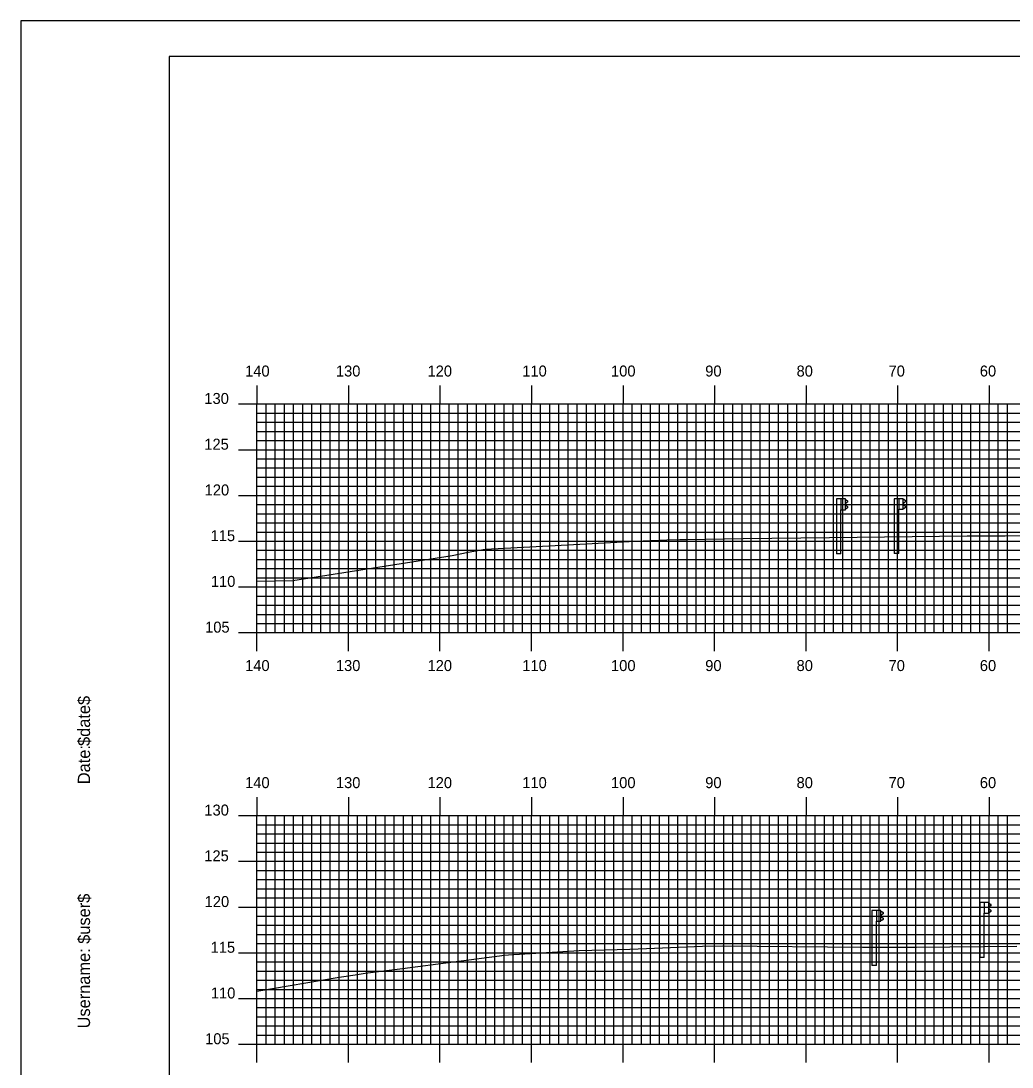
# Model space of a CAD drawing. Extents: x 1754314 to 1754654, y 442591 to 442811.
# Drawn here: x 1754314.2 to 1754422.5, y 442696.2 to 442810.5 of the extents above; entities that cross this region are included whole.
import ezdxf

# ---------------------------------------------------------------- set-up
doc = ezdxf.new("R2010")
doc.units = 0
for name, color, linetype in [('BORDER', 7, 'Continuous'), ('H_V ANNOTATION', 7, 'Continuous'), ('M_Guardrail', 7, 'Continuous'), ('M_Roadway_Centerline', 7, 'Continuous'), ('MAJOR', 7, 'Continuous'), ('MINOR', 7, 'Continuous'), ('PLOT BOUNDARY', 7, 'Continuous'), ('S_Roadway_Centerline', 7, 'Continuous')]:
    doc.layers.add(name, color=color, linetype=linetype)

msp = doc.modelspace()

# ---------------------------------------------------------------- linework, layer by layer
at = {"layer": 'BORDER'}
msp.add_lwpolyline([(1754330.4, 442596.67), (1754650.4, 442596.67), (1754650.4, 442806.67), (1754330.4, 442806.67)], close=True, dxfattribs=at)
at = {"layer": 'M_Guardrail'}
for p, q in [((1754403.31, 442758.28), (1754403.31, 442752.28)), ((1754403.81, 442758.28), (1754403.31, 442758.28)), ((1754404.29, 442758.28), (1754403.81, 442758.28)), ((1754403.81, 442758.28), (1754403.81, 442757.11)), ((1754404.29, 442757.11), (1754404.29, 442758.28)), ((1754404.29, 442758.21), (1754404.38, 442758.19)), ((1754404.31, 442757.74), (1754404.31, 442757.65)), ((1754404.54, 442757.94), (1754404.34, 442757.81)), ((1754404.34, 442757.59), (1754404.54, 442757.45)), ((1754404.39, 442758.19), (1754404.54, 442758.09)), ((1754409.63, 442758.31), (1754409.63, 442752.31)), ((1754410.13, 442758.31), (1754409.63, 442758.31)), ((1754410.62, 442758.31), (1754410.13, 442758.31)), ((1754410.13, 442758.31), (1754410.13, 442757.15)), ((1754410.62, 442757.15), (1754410.62, 442758.31)), ((1754410.62, 442758.24), (1754410.7, 442758.23)), ((1754410.63, 442757.78), (1754410.63, 442757.69)), ((1754410.86, 442757.98), (1754410.66, 442757.84)), ((1754410.66, 442757.62), (1754410.86, 442757.48)), ((1754410.71, 442758.22), (1754410.86, 442758.12)), ((1754410.86, 442757.34), (1754410.71, 442757.24)), ((1754403.81, 442752.28), (1754403.81, 442757.11)), ((1754403.81, 442757.11), (1754404.29, 442757.11)), ((1754404.38, 442757.2), (1754404.29, 442757.19)), ((1754404.54, 442757.31), (1754404.39, 442757.21)), ((1754410.13, 442752.31), (1754410.13, 442757.15)), ((1754410.13, 442757.15), (1754410.62, 442757.15)), ((1754410.7, 442757.23), (1754410.62, 442757.22)), ((1754403.81, 442752.28), (1754403.31, 442752.28)), ((1754410.13, 442752.31), (1754409.63, 442752.31)), ((1754418.97, 442714.16), (1754418.97, 442708.16)), ((1754419.46, 442714.16), (1754418.97, 442714.16)), ((1754419.95, 442714.16), (1754419.46, 442714.16)), ((1754419.46, 442714.16), (1754419.46, 442712.99)), ((1754419.95, 442712.99), (1754419.95, 442714.16)), ((1754419.95, 442714.08), (1754420.03, 442714.07)), ((1754420.05, 442714.06), (1754420.19, 442713.96)), ((1754407.2, 442713.28), (1754407.2, 442707.28)), ((1754407.69, 442713.28), (1754407.2, 442713.28)), ((1754408.18, 442713.28), (1754407.69, 442713.28)), ((1754407.69, 442713.28), (1754407.69, 442712.11)), ((1754408.18, 442712.11), (1754408.18, 442713.28)), ((1754408.18, 442713.21), (1754408.27, 442713.19)), ((1754408.2, 442712.74), (1754408.2, 442712.65)), ((1754408.43, 442712.94), (1754408.23, 442712.81)), ((1754408.28, 442713.19), (1754408.43, 442713.09)), ((1754419.46, 442708.16), (1754419.46, 442712.99)), ((1754419.46, 442712.99), (1754419.95, 442712.99)), ((1754420.03, 442713.08), (1754419.95, 442713.06)), ((1754419.96, 442713.62), (1754419.96, 442713.53)), ((1754420.19, 442713.82), (1754420, 442713.68)), ((1754420, 442713.46), (1754420.19, 442713.33)), ((1754420.19, 442713.18), (1754420.05, 442713.08)), ((1754407.69, 442707.28), (1754407.69, 442712.11)), ((1754407.69, 442712.11), (1754408.18, 442712.11)), ((1754408.27, 442712.2), (1754408.18, 442712.19)), ((1754408.23, 442712.59), (1754408.43, 442712.45)), ((1754408.43, 442712.31), (1754408.28, 442712.21)), ((1754419.46, 442708.16), (1754418.97, 442708.16)), ((1754407.69, 442707.28), (1754407.2, 442707.28))]:
    msp.add_line(p, q, dxfattribs=at)
for centre, major_axis, start_param, end_param in [((1754404.39, 442757.74), (-0.0789, 0), 5.323254, 6.283185), ((1754404.39, 442757.65), (-0.0789, 0), 6.283185, 7.243116), ((1754404.37, 442758.15), (0.0417, 0), 0.959931, 1.396263), ((1754404.49, 442758.01), (0.0877, 0), 5.323254, 7.243116), ((1754404.49, 442757.38), (0.0877, 0), 5.323254, 7.243116), ((1754410.71, 442757.78), (-0.0789, 0), 5.323254, 6.283185), ((1754410.71, 442757.69), (-0.0789, 0), 6.283185, 7.243116), ((1754410.69, 442758.19), (0.0417, 0), 0.959931, 1.396263), ((1754410.81, 442758.05), (0.0877, 0), 5.323254, 7.243116), ((1754410.81, 442757.41), (0.0877, 0), 5.323254, 7.243116), ((1754404.37, 442757.24), (0.0417, 0), 4.886922, 5.323254), ((1754410.69, 442757.28), (0.0417, 0), 4.886922, 5.323254), ((1754420.03, 442714.03), (0.0417, 0), 0.959931, 1.396263), ((1754420.14, 442713.89), (0.0877, 0), 5.323254, 7.243116), ((1754408.28, 442712.74), (-0.0789, 0), 5.323254, 6.283185), ((1754408.26, 442713.15), (0.0417, 0), 0.959931, 1.396263), ((1754408.38, 442713.01), (0.0877, 0), 5.323254, 7.243116), ((1754420.04, 442713.62), (-0.0789, 0), 5.323254, 6.283185), ((1754420.04, 442713.53), (-0.0789, 0), 6.283185, 7.243116), ((1754420.03, 442713.12), (0.0417, 0), 4.886922, 5.323254), ((1754420.14, 442713.26), (0.0877, 0), 5.323254, 7.243116), ((1754408.28, 442712.65), (-0.0789, 0), 6.283185, 7.243116), ((1754408.26, 442712.24), (0.0417, 0), 4.886922, 5.323254), ((1754408.38, 442712.38), (0.0877, 0), 5.323254, 7.243116)]:
    msp.add_ellipse(centre, major_axis=major_axis, ratio=0.995501, start_param=start_param, end_param=end_param, dxfattribs=at)
at = {"layer": 'MAJOR'}
for p, q in [((1754340, 442770.67), (1754340, 442768.67)), ((1754350, 442770.67), (1754350, 442768.67)), ((1754360, 442770.67), (1754360, 442768.67)), ((1754370, 442770.67), (1754370, 442768.67)), ((1754380, 442770.67), (1754380, 442768.67)), ((1754390, 442770.67), (1754390, 442768.67)), ((1754400, 442770.67), (1754400, 442768.67)), ((1754410, 442770.67), (1754410, 442768.67)), ((1754420, 442770.67), (1754420, 442768.67)), ((1754338, 442768.67), (1754340, 442768.67)), ((1754340, 442768.67), (1754620, 442768.67)), ((1754340, 442743.67), (1754340, 442768.67)), ((1754340, 442743.67), (1754340, 442768.67)), ((1754340, 442768.67), (1754620, 442768.67)), ((1754350, 442743.67), (1754350, 442768.67)), ((1754360, 442743.67), (1754360, 442768.67)), ((1754370, 442743.67), (1754370, 442768.67)), ((1754380, 442743.67), (1754380, 442768.67)), ((1754390, 442743.67), (1754390, 442768.67)), ((1754400, 442743.67), (1754400, 442768.67)), ((1754410, 442743.67), (1754410, 442768.67)), ((1754420, 442743.67), (1754420, 442768.67)), ((1754338, 442763.67), (1754340, 442763.67)), ((1754340, 442763.67), (1754620, 442763.67)), ((1754338, 442758.67), (1754340, 442758.67)), ((1754340, 442758.67), (1754620, 442758.67)), ((1754338, 442753.67), (1754340, 442753.67)), ((1754340, 442753.67), (1754620, 442753.67)), ((1754338, 442748.67), (1754340, 442748.67)), ((1754340, 442748.67), (1754620, 442748.67)), ((1754338, 442743.67), (1754340, 442743.67)), ((1754340, 442743.67), (1754620, 442743.67)), ((1754340, 442743.67), (1754620, 442743.67)), ((1754340, 442741.66), (1754340, 442743.67)), ((1754350, 442741.66), (1754350, 442743.67)), ((1754360, 442741.66), (1754360, 442743.67)), ((1754370, 442741.66), (1754370, 442743.67)), ((1754380, 442741.66), (1754380, 442743.67)), ((1754390, 442741.66), (1754390, 442743.67)), ((1754400, 442741.66), (1754400, 442743.67)), ((1754410, 442741.66), (1754410, 442743.67)), ((1754420, 442741.66), (1754420, 442743.67)), ((1754340, 442725.67), (1754340, 442723.67)), ((1754350, 442725.67), (1754350, 442723.67)), ((1754360, 442725.67), (1754360, 442723.67)), ((1754370, 442725.67), (1754370, 442723.67)), ((1754380, 442725.67), (1754380, 442723.67)), ((1754390, 442725.67), (1754390, 442723.67)), ((1754400, 442725.67), (1754400, 442723.67)), ((1754410, 442725.67), (1754410, 442723.67)), ((1754420, 442725.67), (1754420, 442723.67)), ((1754338, 442723.67), (1754340, 442723.67)), ((1754340, 442723.67), (1754620, 442723.67)), ((1754340, 442698.67), (1754340, 442723.67)), ((1754340, 442698.67), (1754340, 442723.67)), ((1754340, 442723.67), (1754620, 442723.67)), ((1754350, 442698.67), (1754350, 442723.67)), ((1754360, 442698.67), (1754360, 442723.67)), ((1754370, 442698.67), (1754370, 442723.67)), ((1754380, 442698.67), (1754380, 442723.67)), ((1754390, 442698.67), (1754390, 442723.67)), ((1754400, 442698.67), (1754400, 442723.67)), ((1754410, 442698.67), (1754410, 442723.67)), ((1754420, 442698.67), (1754420, 442723.67)), ((1754338, 442718.67), (1754340, 442718.67)), ((1754340, 442718.67), (1754620, 442718.67)), ((1754338, 442713.67), (1754340, 442713.67)), ((1754340, 442713.67), (1754620, 442713.67)), ((1754338, 442708.67), (1754340, 442708.67)), ((1754340, 442708.67), (1754620, 442708.67)), ((1754338, 442703.67), (1754340, 442703.67)), ((1754340, 442703.67), (1754620, 442703.67)), ((1754338, 442698.67), (1754340, 442698.67)), ((1754340, 442698.67), (1754620, 442698.67)), ((1754340, 442698.67), (1754620, 442698.67)), ((1754340, 442696.66), (1754340, 442698.67)), ((1754350, 442696.66), (1754350, 442698.67)), ((1754360, 442696.66), (1754360, 442698.67)), ((1754370, 442696.66), (1754370, 442698.67)), ((1754380, 442696.66), (1754380, 442698.67)), ((1754390, 442696.66), (1754390, 442698.67)), ((1754400, 442696.66), (1754400, 442698.67)), ((1754410, 442696.66), (1754410, 442698.67)), ((1754420, 442696.66), (1754420, 442698.67))]:
    msp.add_line(p, q, dxfattribs=at)
at = {"layer": 'MINOR'}
for p, q in [((1754340, 442767.67), (1754620, 442767.67)), ((1754340, 442767.67), (1754342.01, 442767.67)), ((1754341, 442743.67), (1754341, 442768.67)), ((1754342, 442743.67), (1754342, 442768.67)), ((1754343, 442743.67), (1754343, 442768.67)), ((1754344, 442743.67), (1754344, 442768.67)), ((1754345, 442743.67), (1754345, 442768.67)), ((1754346, 442743.67), (1754346, 442768.67)), ((1754347, 442743.67), (1754347, 442768.67)), ((1754348, 442743.67), (1754348, 442768.67)), ((1754349, 442743.67), (1754349, 442768.67)), ((1754351, 442743.67), (1754351, 442768.67)), ((1754352, 442743.67), (1754352, 442768.67)), ((1754353, 442743.67), (1754353, 442768.67)), ((1754354, 442743.67), (1754354, 442768.67)), ((1754355, 442743.67), (1754355, 442768.67)), ((1754356, 442743.67), (1754356, 442768.67)), ((1754357, 442743.67), (1754357, 442768.67)), ((1754358, 442743.67), (1754358, 442768.67)), ((1754359, 442743.67), (1754359, 442768.67)), ((1754361, 442743.67), (1754361, 442768.67)), ((1754362, 442743.67), (1754362, 442768.67)), ((1754363, 442743.67), (1754363, 442768.67)), ((1754364, 442743.67), (1754364, 442768.67)), ((1754365, 442743.67), (1754365, 442768.67)), ((1754366, 442743.67), (1754366, 442768.67)), ((1754367, 442743.67), (1754367, 442768.67)), ((1754368, 442743.67), (1754368, 442768.67)), ((1754369, 442743.67), (1754369, 442768.67)), ((1754371, 442743.67), (1754371, 442768.67)), ((1754372, 442743.67), (1754372, 442768.67)), ((1754373, 442743.67), (1754373, 442768.67)), ((1754374, 442743.67), (1754374, 442768.67)), ((1754375, 442743.67), (1754375, 442768.67)), ((1754376, 442743.67), (1754376, 442768.67)), ((1754377, 442743.67), (1754377, 442768.67)), ((1754378, 442743.67), (1754378, 442768.67)), ((1754379, 442743.67), (1754379, 442768.67)), ((1754381, 442743.67), (1754381, 442768.67)), ((1754382, 442743.67), (1754382, 442768.67)), ((1754383, 442743.67), (1754383, 442768.67)), ((1754384, 442743.67), (1754384, 442768.67)), ((1754385, 442743.67), (1754385, 442768.67)), ((1754386, 442743.67), (1754386, 442768.67)), ((1754387, 442743.67), (1754387, 442768.67)), ((1754388, 442743.67), (1754388, 442768.67)), ((1754389, 442743.67), (1754389, 442768.67)), ((1754391, 442743.67), (1754391, 442768.67)), ((1754392, 442743.67), (1754392, 442768.67)), ((1754393, 442743.67), (1754393, 442768.67)), ((1754394, 442743.67), (1754394, 442768.67)), ((1754395, 442743.67), (1754395, 442768.67)), ((1754396, 442743.67), (1754396, 442768.67)), ((1754397, 442743.67), (1754397, 442768.67)), ((1754398, 442743.67), (1754398, 442768.67)), ((1754399, 442743.67), (1754399, 442768.67)), ((1754401, 442743.67), (1754401, 442768.67)), ((1754402, 442743.67), (1754402, 442768.67)), ((1754403, 442743.67), (1754403, 442768.67)), ((1754404, 442743.67), (1754404, 442768.67)), ((1754405, 442743.67), (1754405, 442768.67)), ((1754406, 442743.67), (1754406, 442768.67)), ((1754407, 442743.67), (1754407, 442768.67)), ((1754408, 442743.67), (1754408, 442768.67)), ((1754409, 442743.67), (1754409, 442768.67)), ((1754411, 442743.67), (1754411, 442768.67)), ((1754412, 442743.67), (1754412, 442768.67)), ((1754413, 442743.67), (1754413, 442768.67)), ((1754414, 442743.67), (1754414, 442768.67)), ((1754415, 442743.67), (1754415, 442768.67)), ((1754416, 442743.67), (1754416, 442768.67)), ((1754417, 442743.67), (1754417, 442768.67)), ((1754418, 442743.67), (1754418, 442768.67)), ((1754419, 442743.67), (1754419, 442768.67)), ((1754421, 442743.67), (1754421, 442768.67)), ((1754422, 442743.67), (1754422, 442768.67)), ((1754340, 442766.67), (1754620, 442766.67)), ((1754340, 442766.67), (1754342.01, 442766.67)), ((1754340, 442765.67), (1754620, 442765.67)), ((1754340, 442765.67), (1754342.01, 442765.67)), ((1754340, 442764.67), (1754620, 442764.67)), ((1754340, 442764.67), (1754342.01, 442764.67)), ((1754340, 442762.67), (1754620, 442762.67)), ((1754340, 442762.67), (1754342.01, 442762.67)), ((1754340, 442761.67), (1754620, 442761.67)), ((1754340, 442761.67), (1754342.01, 442761.67)), ((1754340, 442760.67), (1754620, 442760.67)), ((1754340, 442760.67), (1754342.01, 442760.67)), ((1754340, 442759.67), (1754620, 442759.67)), ((1754340, 442759.67), (1754342.01, 442759.67)), ((1754340, 442757.67), (1754620, 442757.67)), ((1754340, 442757.67), (1754342.01, 442757.67)), ((1754340, 442756.67), (1754620, 442756.67)), ((1754340, 442756.67), (1754342.01, 442756.67)), ((1754340, 442755.67), (1754620, 442755.67)), ((1754340, 442755.67), (1754342.01, 442755.67)), ((1754340, 442754.67), (1754620, 442754.67)), ((1754340, 442754.67), (1754342.01, 442754.67)), ((1754340, 442752.67), (1754620, 442752.67)), ((1754340, 442752.67), (1754342.01, 442752.67)), ((1754340, 442751.67), (1754620, 442751.67)), ((1754340, 442751.67), (1754342.01, 442751.67)), ((1754340, 442750.67), (1754620, 442750.67)), ((1754340, 442750.67), (1754342.01, 442750.67)), ((1754340, 442749.67), (1754620, 442749.67)), ((1754340, 442749.67), (1754342.01, 442749.67)), ((1754340, 442747.67), (1754620, 442747.67)), ((1754340, 442747.67), (1754342.01, 442747.67)), ((1754340, 442746.67), (1754620, 442746.67)), ((1754340, 442746.67), (1754342.01, 442746.67)), ((1754340, 442745.67), (1754620, 442745.67)), ((1754340, 442745.67), (1754342.01, 442745.67)), ((1754340, 442744.67), (1754620, 442744.67)), ((1754340, 442744.67), (1754342.01, 442744.67)), ((1754341, 442698.67), (1754341, 442723.67)), ((1754342, 442698.67), (1754342, 442723.67)), ((1754343, 442698.67), (1754343, 442723.67)), ((1754344, 442698.67), (1754344, 442723.67)), ((1754345, 442698.67), (1754345, 442723.67)), ((1754346, 442698.67), (1754346, 442723.67)), ((1754347, 442698.67), (1754347, 442723.67)), ((1754348, 442698.67), (1754348, 442723.67)), ((1754349, 442698.67), (1754349, 442723.67)), ((1754351, 442698.67), (1754351, 442723.67)), ((1754352, 442698.67), (1754352, 442723.67)), ((1754353, 442698.67), (1754353, 442723.67)), ((1754354, 442698.67), (1754354, 442723.67)), ((1754355, 442698.67), (1754355, 442723.67)), ((1754356, 442698.67), (1754356, 442723.67)), ((1754357, 442698.67), (1754357, 442723.67)), ((1754358, 442698.67), (1754358, 442723.67)), ((1754359, 442698.67), (1754359, 442723.67)), ((1754361, 442698.67), (1754361, 442723.67)), ((1754362, 442698.67), (1754362, 442723.67)), ((1754363, 442698.67), (1754363, 442723.67)), ((1754364, 442698.67), (1754364, 442723.67)), ((1754365, 442698.67), (1754365, 442723.67)), ((1754366, 442698.67), (1754366, 442723.67)), ((1754367, 442698.67), (1754367, 442723.67)), ((1754368, 442698.67), (1754368, 442723.67)), ((1754369, 442698.67), (1754369, 442723.67)), ((1754371, 442698.67), (1754371, 442723.67)), ((1754372, 442698.67), (1754372, 442723.67)), ((1754373, 442698.67), (1754373, 442723.67)), ((1754374, 442698.67), (1754374, 442723.67)), ((1754375, 442698.67), (1754375, 442723.67)), ((1754376, 442698.67), (1754376, 442723.67)), ((1754377, 442698.67), (1754377, 442723.67)), ((1754378, 442698.67), (1754378, 442723.67)), ((1754379, 442698.67), (1754379, 442723.67)), ((1754381, 442698.67), (1754381, 442723.67)), ((1754382, 442698.67), (1754382, 442723.67)), ((1754383, 442698.67), (1754383, 442723.67)), ((1754384, 442698.67), (1754384, 442723.67)), ((1754385, 442698.67), (1754385, 442723.67)), ((1754386, 442698.67), (1754386, 442723.67)), ((1754387, 442698.67), (1754387, 442723.67)), ((1754388, 442698.67), (1754388, 442723.67)), ((1754389, 442698.67), (1754389, 442723.67)), ((1754391, 442698.67), (1754391, 442723.67)), ((1754392, 442698.67), (1754392, 442723.67)), ((1754393, 442698.67), (1754393, 442723.67)), ((1754394, 442698.67), (1754394, 442723.67)), ((1754395, 442698.67), (1754395, 442723.67)), ((1754396, 442698.67), (1754396, 442723.67)), ((1754397, 442698.67), (1754397, 442723.67)), ((1754398, 442698.67), (1754398, 442723.67)), ((1754399, 442698.67), (1754399, 442723.67)), ((1754401, 442698.67), (1754401, 442723.67)), ((1754402, 442698.67), (1754402, 442723.67)), ((1754403, 442698.67), (1754403, 442723.67)), ((1754404, 442698.67), (1754404, 442723.67)), ((1754405, 442698.67), (1754405, 442723.67)), ((1754406, 442698.67), (1754406, 442723.67)), ((1754407, 442698.67), (1754407, 442723.67)), ((1754408, 442698.67), (1754408, 442723.67)), ((1754409, 442698.67), (1754409, 442723.67)), ((1754411, 442698.67), (1754411, 442723.67)), ((1754412, 442698.67), (1754412, 442723.67)), ((1754413, 442698.67), (1754413, 442723.67)), ((1754414, 442698.67), (1754414, 442723.67)), ((1754415, 442698.67), (1754415, 442723.67)), ((1754416, 442698.67), (1754416, 442723.67)), ((1754417, 442698.67), (1754417, 442723.67)), ((1754418, 442698.67), (1754418, 442723.67)), ((1754419, 442698.67), (1754419, 442723.67)), ((1754421, 442698.67), (1754421, 442723.67)), ((1754422, 442698.67), (1754422, 442723.67)), ((1754340, 442722.67), (1754620, 442722.67)), ((1754340, 442722.67), (1754342.01, 442722.67)), ((1754340, 442721.67), (1754620, 442721.67)), ((1754340, 442721.67), (1754342.01, 442721.67)), ((1754340, 442720.67), (1754620, 442720.67)), ((1754340, 442720.67), (1754342.01, 442720.67)), ((1754340, 442719.67), (1754620, 442719.67)), ((1754340, 442719.67), (1754342.01, 442719.67)), ((1754340, 442717.67), (1754620, 442717.67)), ((1754340, 442717.67), (1754342.01, 442717.67)), ((1754340, 442716.67), (1754620, 442716.67)), ((1754340, 442716.67), (1754342.01, 442716.67)), ((1754340, 442715.67), (1754620, 442715.67)), ((1754340, 442715.67), (1754342.01, 442715.67)), ((1754340, 442714.67), (1754620, 442714.67)), ((1754340, 442714.67), (1754342.01, 442714.67)), ((1754340, 442712.67), (1754620, 442712.67)), ((1754340, 442712.67), (1754342.01, 442712.67)), ((1754340, 442711.67), (1754620, 442711.67)), ((1754340, 442711.67), (1754342.01, 442711.67)), ((1754340, 442710.67), (1754620, 442710.67)), ((1754340, 442710.67), (1754342.01, 442710.67)), ((1754340, 442709.67), (1754620, 442709.67)), ((1754340, 442709.67), (1754342.01, 442709.67)), ((1754340, 442707.67), (1754620, 442707.67)), ((1754340, 442707.67), (1754342.01, 442707.67)), ((1754340, 442706.67), (1754620, 442706.67)), ((1754340, 442706.67), (1754342.01, 442706.67)), ((1754340, 442705.67), (1754620, 442705.67)), ((1754340, 442705.67), (1754342.01, 442705.67)), ((1754340, 442704.67), (1754620, 442704.67)), ((1754340, 442704.67), (1754342.01, 442704.67)), ((1754340, 442702.67), (1754620, 442702.67)), ((1754340, 442702.67), (1754342.01, 442702.67)), ((1754340, 442701.67), (1754620, 442701.67)), ((1754340, 442701.67), (1754342.01, 442701.67)), ((1754340, 442700.67), (1754620, 442700.67)), ((1754340, 442700.67), (1754342.01, 442700.67)), ((1754340, 442699.67), (1754620, 442699.67)), ((1754340, 442699.67), (1754342.01, 442699.67))]:
    msp.add_line(p, q, dxfattribs=at)
at = {"layer": 'PLOT BOUNDARY'}
msp.add_lwpolyline([(1754314.22, 442590.55), (1754654.22, 442590.55), (1754654.22, 442810.55), (1754314.22, 442810.55)], close=True, dxfattribs=at)
at = {"layer": 'S_Roadway_Centerline'}
for points in [[(1754340, 442749.29), (1754343.91, 442749.38), (1754361.34, 442752.12), (1754363.09, 442752.48), (1754364.95, 442752.79), (1754367.04, 442752.92), (1754372.58, 442753.2), (1754381.31, 442753.67), (1754384.77, 442753.82), (1754386.21, 442753.84), (1754387.02, 442753.84), (1754393.11, 442753.97), (1754402.57, 442754.06), (1754417.61, 442754.24), (1754421.76, 442754.24), (1754423.56, 442754.3)], [(1754340, 442704.47), (1754349, 442706.01), (1754350.74, 442706.26), (1754351.81, 442706.44), (1754355.91, 442706.94), (1754367.05, 442708.39), (1754367.47, 442708.44), (1754372.85, 442708.77), (1754375.21, 442708.9), (1754380.74, 442709.07), (1754382.56, 442709.15), (1754388.67, 442709.39), (1754390.82, 442709.44), (1754406.17, 442709.29), (1754410.26, 442709.28), (1754412.07, 442709.27), (1754423.02, 442709.39)]]:
    msp.add_lwpolyline(points, dxfattribs=at)

# ---------------------------------------------------------------- texts
at = {"layer": 'BORDER'}
for s, p in [('$date$', (1754321.77, 442731.28)), ('$date$', (1754321.77, 442731.28)), ('Date:', (1754321.77, 442727.1)), ('Date:', (1754321.77, 442727.1)), ('$user$', (1754321.77, 442709.65)), ('$user$', (1754321.77, 442709.65)), ('Username:', (1754321.77, 442700.4)), ('Username:', (1754321.77, 442700.4))]:
    msp.add_text(s, height=1.339, rotation=90, dxfattribs=at).set_placement(p)
at = {"layer": 'H_V ANNOTATION'}
for s, p in [('140', (1754338.71, 442771.67)), ('130', (1754348.63, 442771.67)), ('120', (1754358.64, 442771.67)), ('110', (1754368.99, 442771.67)), ('100', (1754378.69, 442771.67)), ('90', (1754388.98, 442771.67)), ('80', (1754398.96, 442771.67)), ('70', (1754409.01, 442771.67)), ('60', (1754418.98, 442771.67)), ('130', (1754334.26, 442768.67)), ('125', (1754334.25, 442763.67)), ('120', (1754334.29, 442758.67)), ('115', (1754334.94, 442753.67)), ('110', (1754334.97, 442748.67)), ('105', (1754334.34, 442743.67)), ('140', (1754338.71, 442739.47)), ('130', (1754348.63, 442739.47)), ('120', (1754358.64, 442739.47)), ('110', (1754368.99, 442739.47)), ('100', (1754378.69, 442739.47)), ('90', (1754388.98, 442739.47)), ('80', (1754398.96, 442739.47)), ('70', (1754409.01, 442739.47)), ('60', (1754418.98, 442739.47)), ('140', (1754338.71, 442726.67)), ('130', (1754348.63, 442726.67)), ('120', (1754358.64, 442726.67)), ('110', (1754368.99, 442726.67)), ('100', (1754378.69, 442726.67)), ('90', (1754388.98, 442726.67)), ('80', (1754398.96, 442726.67)), ('70', (1754409.01, 442726.67)), ('60', (1754418.98, 442726.67)), ('130', (1754334.26, 442723.67)), ('125', (1754334.25, 442718.67)), ('120', (1754334.29, 442713.67)), ('115', (1754334.94, 442708.67)), ('110', (1754334.97, 442703.67)), ('105', (1754334.34, 442698.67))]:
    msp.add_text(s, height=1.2, dxfattribs=at).set_placement(p)
at = {"layer": 'M_Roadway_Centerline'}
for s, p in [('C', (1754384.76, 442753.82)), ('L', (1754384.76, 442753.81)), ('C', (1754388.66, 442709.39)), ('L', (1754388.66, 442709.38))]:
    msp.add_text(s, height=0.0146, dxfattribs=at).set_placement(p)
at = {"layer": 'MAJOR'}
for p in [(1754340, 442743.67), (1754340, 442698.67)]:
    msp.add_text('-', height=0.012, dxfattribs=at).set_placement(p)

doc.saveas('drawing.dxf')
